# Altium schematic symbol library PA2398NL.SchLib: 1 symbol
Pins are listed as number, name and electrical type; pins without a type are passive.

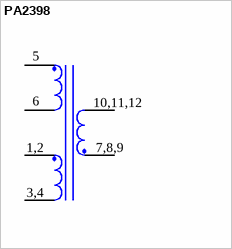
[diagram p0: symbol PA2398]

## PA2398
designator X?, comment PA2398NL
Manufacturer: Pulse Electronics; SymbolVersion: use current date i.e. 2008-05-20; SymbolCreator: Use a-id; CompType: Transformer; U/M: EA; Description: Transformer, 307 uH, SMT; Value: 307 uH
pins: 1, 2, 3, 4, 5, 6, 7, 8, 9, 10, 11, 12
